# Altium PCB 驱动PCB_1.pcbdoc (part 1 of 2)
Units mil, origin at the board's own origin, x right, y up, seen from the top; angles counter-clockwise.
Board outline 1900 x 3705 mil, 2 copper layers (Top Layer, Bottom Layer); 43 components, 46 nets, 190 pads, 128 vias.
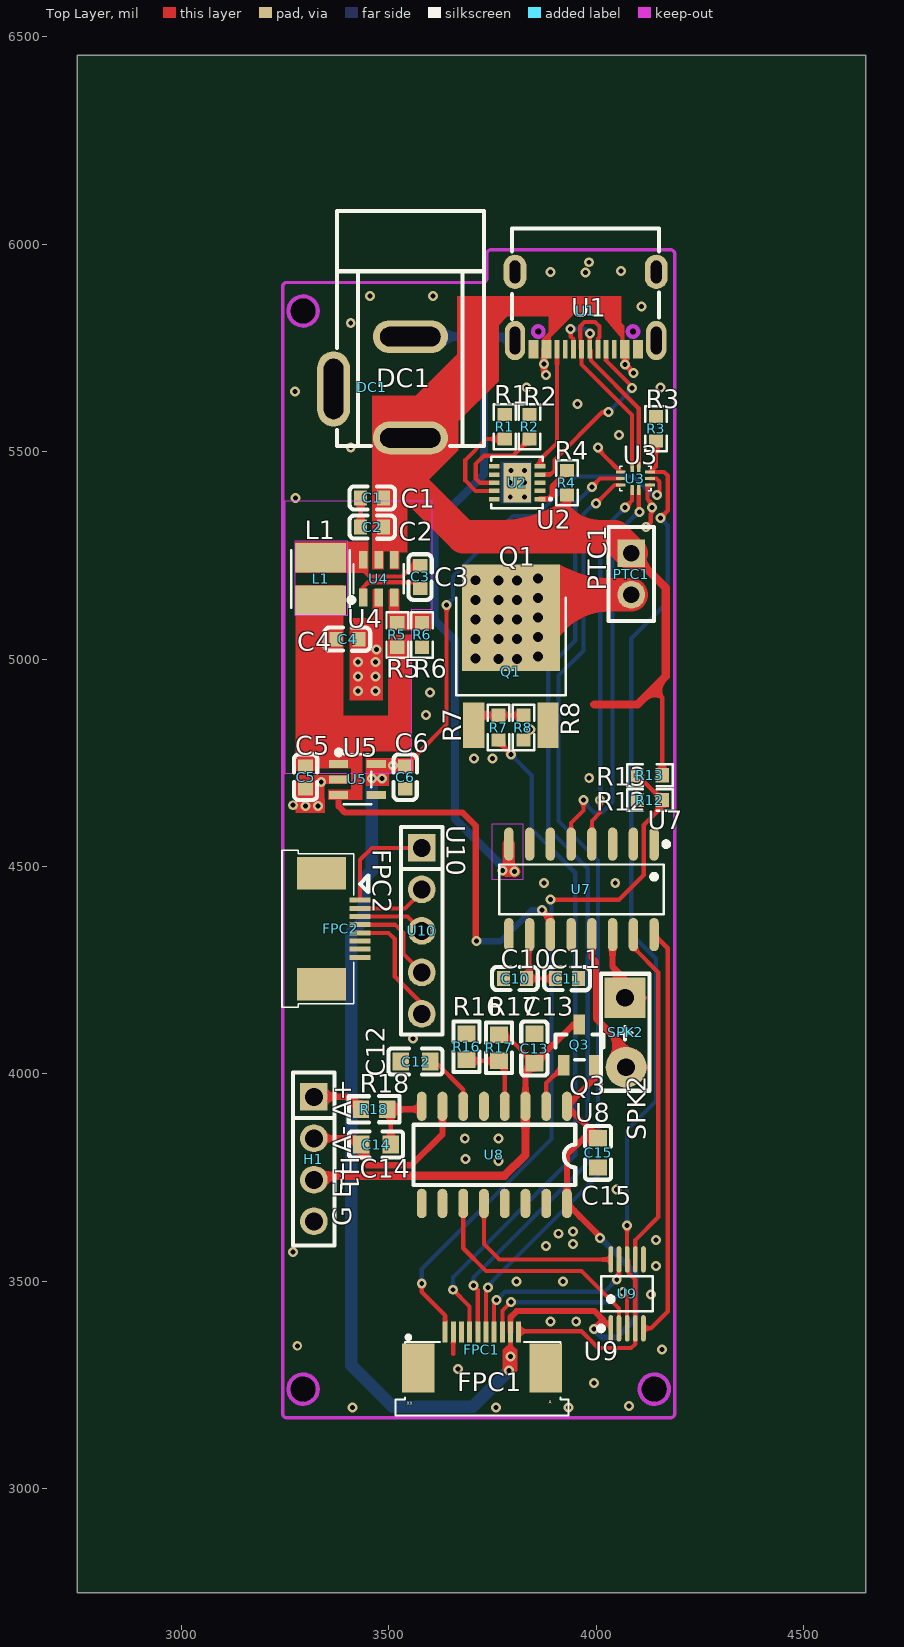
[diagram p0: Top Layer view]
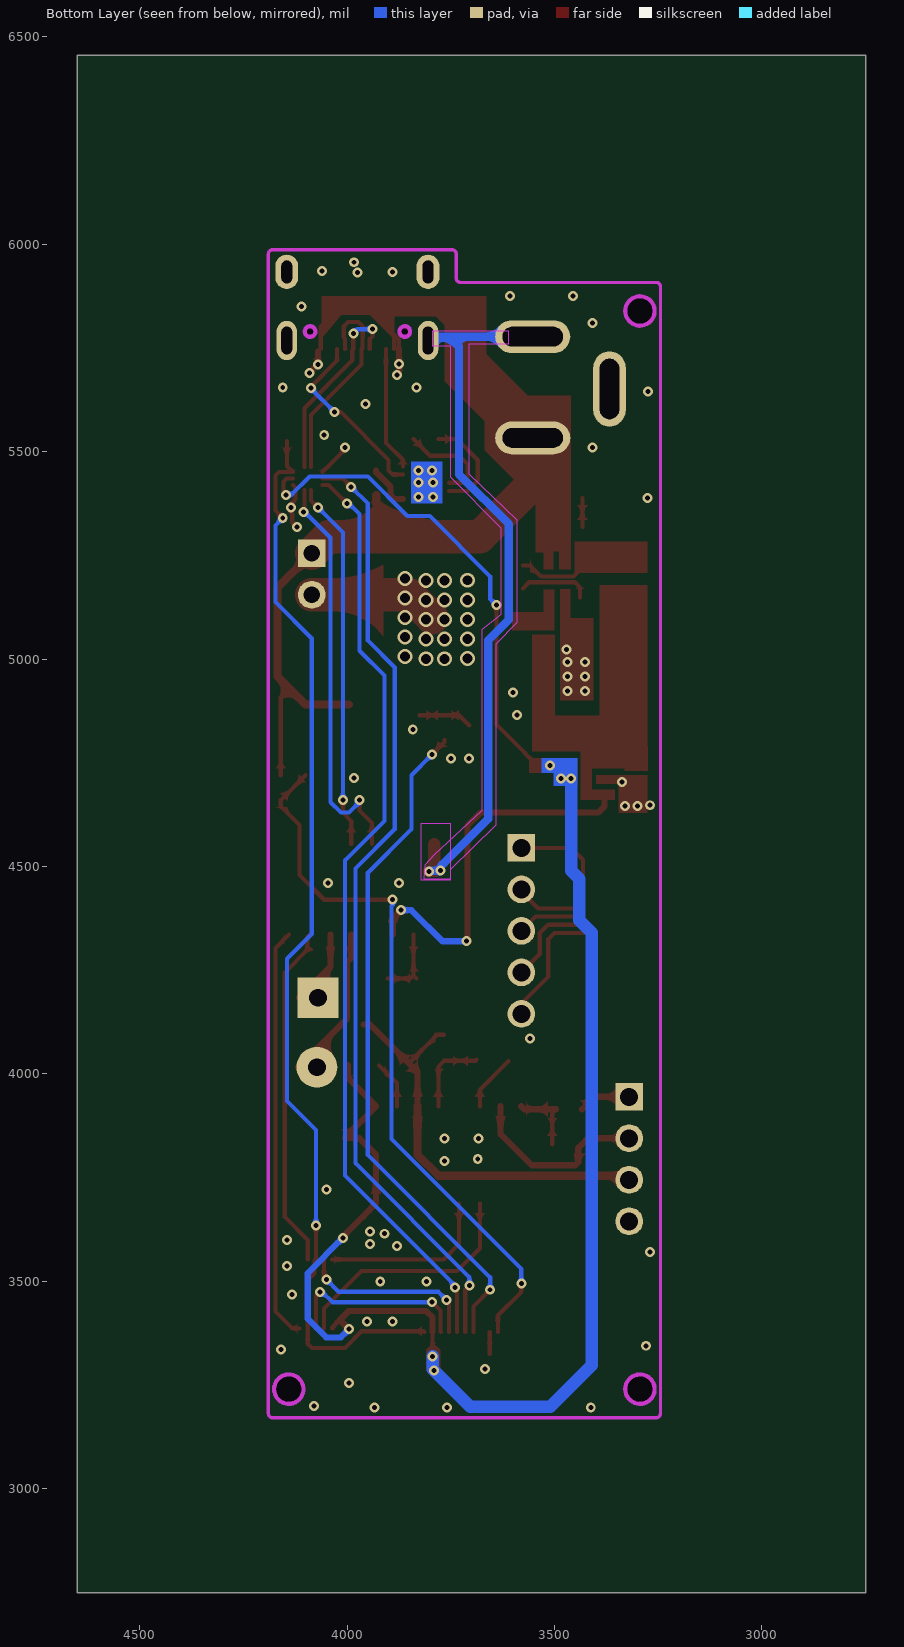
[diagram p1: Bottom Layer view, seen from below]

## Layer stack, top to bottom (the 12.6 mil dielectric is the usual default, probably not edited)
Top Layer: signal copper (thickness not stored)
Dielectric: dielectric 12.6, FR-4, Dk 4.8
Bottom Layer: signal copper (thickness not stored)

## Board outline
4650,2750 2750,2750 2750,6455 4650,6455
cut-out: 3329.43,5838.89 ccw(c3294,5838.67) 3258.57,5838.89 ccw(c3294,5839.11)
cut-out: 3329.43,3240.47 ccw(c3294,3240.25) 3258.57,3240.47 ccw(c3294,3240.69)
cut-out: 4175.89,3240.47 ccw(c4140.45,3240.47) 4105.02,3240.47 ccw(c4140.45,3240.47)

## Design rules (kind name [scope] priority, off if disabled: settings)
BoardOutlineClearance copperThickness1oz [All] p0: genericclearance=10 ignorepadtopadclearanceinfootprint=FALSE except(0: Arc-SplitContinuation Track-SplitContinuation SMDPad-SplitContinuation THPad-SplitContinuation Via-SplitContinuation Fill-SplitContinuation Poly-SplitContinuation Region-SplitContinuation Text-SplitContinuation; 6: Track-CutoutEdge SMDPad-CutoutEdge THPad-CutoutEdge Via-CutoutEdge Region-CutoutEdge; 11.8: Track-OutlineEdge SMDPad-OutlineEdge THPad-OutlineEdge Via-OutlineEdge Fill-OutlineEdge Region-OutlineEdge Poly-OutlineEdge Text-OutlineEdge Fill-CutoutEdge)
BoardOutlineClearance copperThickness2oz [All] p0: genericclearance=10 ignorepadtopadclearanceinfootprint=FALSE except(0: Arc-SplitContinuation Track-SplitContinuation SMDPad-SplitContinuation THPad-SplitContinuation Via-SplitContinuation Fill-SplitContinuation Poly-SplitContinuation Region-SplitContinuation Text-SplitContinuation; 6: Track-CutoutEdge SMDPad-CutoutEdge THPad-CutoutEdge Via-CutoutEdge Region-CutoutEdge; 11.8: Track-OutlineEdge SMDPad-OutlineEdge THPad-OutlineEdge Via-OutlineEdge Fill-OutlineEdge Region-OutlineEdge Poly-OutlineEdge Text-OutlineEdge Fill-CutoutEdge)
Clearance copperThickness1oz [(InNet('GND') OR InNet('3V3') OR InNet('ADC_VIN') OR InNet('$2N1457') OR InNet('$2N1458') OR InNet('VIN') OR InNet('5V') OR InNet('$2N1719') OR InNet('$2N3514') OR InNet('$2N3517') OR InNet('A-') OR InNet('ESP_TX') OR InNet('ESP_RX') OR InNet('DN1') OR InNet('DP1') OR InNet('A+') OR InNet('E+') OR InNet('$2N173') OR InNet('$2N169') OR InNet('$2N860') OR InNet('$2N846') OR InNet('$2N1461') OR InNet('$2N861') OR InNet('DAC') OR InNet('$2N3512') OR InNet('SPK2') OR InNet('SPK1') OR InNet('SCK') OR InNet('DOUT') OR InNet('CC1') OR InNet('DN') OR InNet('DP') OR InNet('CC2') OR InNet('USBDM') OR InNet('USBDP') OR InNet('CH7800_RX') OR InNet('CH7800_TX') OR InNet('SW') OR InNet('PTC') OR InNet('$2N3503') OR InNet('$2N3080') OR InNet('GPIO17') OR InNet('GPIO16') OR InNet('GPIO15') OR InNet('GPIO14') OR InNet('GPIO8'))] p1: gap=7 ignorepadtopadclearanceinfootprint=FALSE except(4: Track-Track; 6: Track-SMDPad SMDPad-SMDPad Track-THPad SMDPad-THPad THPad-THPad Track-Via SMDPad-Via THPad-Via Via-Via SMDPad-Fill THPad-Fill Via-Fill Fill-Fill Track-Region SMDPad-Region THPad-Region Via-Region Region-Region Track-Poly SMDPad-Poly THPad-Poly Via-Poly Fill-Poly Region-Poly Poly-Poly Track-Text SMDPad-Text THPad-Text Via-Text Fill-Text Region-Text Poly-Text Text-Text; 6.9: Track-Hole SMDPad-Hole THPad-Hole Via-Hole Fill-Hole Region-Hole Poly-Hole Text-Hole Sheet-Hole; 11.8: Track-Fill Fill-Region Track-Sheet SMDPad-Sheet THPad-Sheet Via-Sheet Fill-Sheet Region-Sheet Poly-Sheet Text-Sheet)
Clearance copperThickness2oz [All] p1: gap=7 ignorepadtopadclearanceinfootprint=FALSE except(6: Track-SMDPad SMDPad-SMDPad Track-THPad SMDPad-THPad THPad-THPad Track-Via SMDPad-Via THPad-Via Via-Via SMDPad-Fill THPad-Fill Via-Fill Fill-Fill Track-Region SMDPad-Region THPad-Region Via-Region Region-Region Track-Poly SMDPad-Poly THPad-Poly Via-Poly Fill-Poly Region-Poly Poly-Poly Track-Text SMDPad-Text THPad-Text Via-Text Fill-Text Region-Text Poly-Text Text-Text; 6.9: Track-Hole SMDPad-Hole THPad-Hole Via-Hole Fill-Hole Region-Hole Poly-Hole Text-Hole Sheet-Hole; 8: Track-Track; 11.8: Track-Fill Fill-Region Track-Sheet SMDPad-Sheet THPad-Sheet Via-Sheet Fill-Sheet Region-Sheet Poly-Sheet Text-Sheet)
DiffPairsRouting differentialPair [All] p1: maxuncoupledlength=10 minlimit=6 maxlimit=6 mostfreqgap=6 toplayer_minwidth=5 toplayer_prefwidth=10 toplayer_maxwidth=100 bottomlayer_minwidth=5 bottomlayer_prefwidth=10 bottomlayer_maxwidth=100
PasteMaskExpansion pasteMaskExpansion [All] p1: expansion=0
PlaneConnect innerPlane [All] p1: planeconnectstyle=Relief reliefexpansion=20 reliefentries=4 reliefconductorwidth=10 reliefairgap=10
PolygonConnect copperRegion [All] p1: connectstyle=Relief reliefentries=4 reliefconductorwidth=10 polygonreliefangle="90 Angle" airgapwidth=10
RoutingVias viaSize [All] p1: viastyle="Through Hole" holewidth=12.0078 minholewidth=11.811 maxholewidth=248.0314 width=24.0158 minwidth=19.685 maxwidth=393.7008
SolderMaskExpansion solderMaskExpansion [All] p1: useseparateexpansions=TRUE expansion=2 expansionbottom=2
Width copperThickness1oz [All] p1: maxlimit=100 minlimit=5 preferedwidth=10
Width copperThickness2oz [All] p1: maxlimit=100 minlimit=8 preferedwidth=10

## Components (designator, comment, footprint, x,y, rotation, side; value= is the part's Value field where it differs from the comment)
C1 "CC0603KRX7R9BB104" C0603#1 3460.47,5388.23 r180 top
C2 "CL10A106MA8NRNC" C0603#1 3460.47,5318.23 r180 top
C3 "CC0603KRX7R9BB104" C0603#1 3576.08,5198.01 r90 top
C4 "CC0603KRX7R9BB104" C0603#1 3401.08,5048.01 r0 top
C5 "CL10A106MA8NRNC" C0603#1 3300,4715 r270 top
C6 "CL10A106MA8NRNC" C0603#1 3540,4715 r270 top
C10 "CAP_0603" C0603#1 3805,4230 r0 top
C11 "CAP_0603" C0603#1 3930,4230 r180 top
C12 "100nF" C0603#2 3565,4030 r180 top
C13 "10uF" C0603#2 3851.24,4061.24 r90 top
C14 "100nF" C0603#2 3470,3830 r180 top
C15 "10uF" C0603#2 4005,3810 r270 top
DC1 "DC005" DC-IN-TH_DC005 3460,5655 r270 top locked
FPC1 "F0501-T-10-20T-R" FPC-SMD_F0501-T-10-20T-R 3725,3335 r0 top
FPC2 "F0501-T-08-20T-R" FPC-SMD_8P-P0.50_L4.4-W9.6 3385,4350 r270 top
H1 "HDR-F_2.54_1x4P" hdr-th_4p-p2.54-v-f 3320,3795 r270 top
L1 "CD32-4R7M 4.7UH" IND-SMD_L3.5-W3.0 3336.08,5193.01 r90 top
PTC1 "HDR-F_2.54_1x2P" HDR-TH_2P-P2.54-V-F 4085,5205 r270 top
Q1 "AOD4184L" TO-252-2_L6.6-W6.1-P4.57-LS9.9-TL-CW 3795,4970 r90 top
Q3 "S8550" SOT-23-3_L2.9-W1.6-P1.90-LS2.8-BR 3960,4070 r270 top
R1 "Res_0603" R0603#1 3780,5560 r90 top
R2 "Res_0603" R0603#1 3840,5560 r90 top
R3 "Res_0603" R0603#1 4145,5555 r270 top
R4 "Res_0603" R0603#1 3930,5425 r270 top
R5 "Res_0603" R0603#1 3521.08,5058.01 r270 top
R6 "Res_0603" R0603#1 3581.08,5058.01 r90 top
R7 "Res_0603" R0603#1 3765,4835 r90 top
R8 "Res_0603" R0603#1 3825,4835 r270 top
R12 "Res_0603" R0603#1 4130,4660 r180 top
R13 "Res_0603" R0603#1 4130,4720 r180 top
R16 "8.2K" R0603#2 3687.88,4065.74 r270 top
R17 "20K" R0603#2 3766.24,4063.24 r90 top
R18 "1K" R0603#2 3465,3915 r0 top
SPK2 "GSPK3013P-8R0.15W" SPK-TH_BD30.0-P15.00-D0.8-L-RD 4070,4100 r270 top
U1 "TYPE-C16PIN母座 板上四脚三次molding" USB-SMD_TYPE-C16PIN 3975,5840 r180 top locked
U2 "HUSB238-002D" TDFN-10_L3.0-W3.0-P0.50-BL-EP 3810,5425 r90 top
U3 "BL1532TQFN" qfn_10 4095,5435 r180 top
U4 "RY8411_C2935411" SOT-23-6_L2.9-W1.6-P0.95-LS2.8-TL 3476.14,5193.63 r90 top
U5 "ME6212C33M5G" SOT-23-5_L3.0-W1.7-P0.95-LS2.8-BL 3425,4710 r270 top
U7 "CH7800" SOP-16_L9.9-W3.9-P1.27-LS6.0-BL 3965,4445 r180 top
U8 "HX711" SOP-16_L10.0-W3.9-P1.27-LS6.0-BL 3755,3805 r180 top
U9 "BL1555MM" MSOP-10_L3.0-W3.0-P0.50-LS5.0-BL 4075,3470 r0 top
U10 "HB-PH3-25415PB2GOP" HDR-TH_5P-P2.54-V-M 3580,4345 r270 top

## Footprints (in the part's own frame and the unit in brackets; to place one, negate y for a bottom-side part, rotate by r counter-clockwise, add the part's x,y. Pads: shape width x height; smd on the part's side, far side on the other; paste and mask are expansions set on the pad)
C0603#1 [mm]
  rect 0.8x0.9 smd: 1(-0.7,0) 2(0.7,0)
  silkscreen extent -1.41,-0.71 1.39,0.72
C0603#2 [mm]
  rect 1x1.1 smd: 1(-0.9,0) 2(0.9,0)
  silkscreen extent -1.65,-0.8 1.65,0.8
DC-IN-TH_DC005 [mm]
  oval 2x4.6 hole 1.2 slot 3.7 at 90 deg: 1(3.1,2.35) 2(-3.1,2.35)
  oval 4.6x2 hole 1.2 slot 3.7 at 0 deg: 3(0.1,-2.35)
  silkscreen extent -10.8,-2.15 3.6,6.85
FPC-SMD_8P-P0.50_L4.4-W9.6 [mm]
  rect 2x3 smd: 0(-3.4,-1.175) 0(3.4,-1.175)
  rect 0.3x1.3 smd: 1(-1.75,1.175) 2(-1.25,1.175) 3(-0.75,1.175) 4(-0.25,1.175) 5(0.25,1.175) 6(0.75,1.175) 7(1.25,1.175) 8(1.75,1.175)
  silkscreen extent -4.8,-3.6 4.8,1.68
FPC-SMD_F0501-T-10-20T-R [mm]
  rect 0.3x1.3 smd: 1(-2.25,1.097) 2(-1.75,1.097) 3(-1.25,1.097) 4(-0.75,1.097) 5(-0.25,1.097) 6(0.25,1.097) 7(0.75,1.097) 8(1.25,1.097) 9(1.75,1.097) 10(2.25,1.097)
  rect 2x3 smd: 11(3.9,-1.097) 12(-3.9,-1.097)
  silkscreen extent -5.3,-4.03 5.3,0.87
HDR-TH_2P-P2.54-V-F [mm]
  rect 1.7x1.7 hole 1: 1(-1.27,0)
  round 1.7 hole 1: 2(1.27,0)
  silkscreen extent -2.88,-1.39 2.88,1.4
hdr-th_4p-p2.54-v-f [mm]
  rect 1.7x1.7 hole 1.1: 1(-3.81,0)
  round 1.7 hole 1.1: 2(-1.27,0) 3(1.27,0) 4(3.81,0)
  silkscreen extent -5.29,-1.27 5.29,1.27
HDR-TH_5P-P2.54-V-M [mm]
  rect 1.7x1.7 hole 1.1: 1(-5.08,0)
  round 1.7 hole 1.1: 2(-2.54,0) 3(0,0) 4(2.54,0) 5(5.08,0)
  silkscreen extent -6.35,-1.27 6.35,1.27
IND-SMD_L3.5-W3.0 [mm]
  rect 1.8x3.12 smd: 1(1.303,0) 2(-1.303,0)
  silkscreen extent -1.75,-1.8 1.75,1.8
MSOP-10_L3.0-W3.0-P0.50-LS5.0-BL [mm]
  oval 0.28x1.62 smd: 1(-1,-2.11) 2(-0.5,-2.11) 3(0,-2.11) 4(0.5,-2.11) 5(1,-2.11) 6(1,2.11) 7(0.5,2.11) 8(0,2.11) 9(-0.5,2.11) 10(-1,2.11)
  silkscreen extent -1.74,-2.26 1.58,1.07
qfn_10 [mm]
  rrect20% 0.2x0.6 smd: 1(-0.2,-0.7) 2(0.2,-0.7) 6(0.2,0.7) 7(-0.2,0.7)
  rrect20% 0.6x0.2 smd: 3(0.9,-0.4) 4(0.9,0) 5(0.9,0.4) 8(-0.9,0.4) 9(-0.9,0) 10(-0.9,-0.4)
  silkscreen extent -0.95,-0.89 0.95,0.75
R0603#1 [mil]
  rect 31.75x34.02 smd: 1(-29.66,0) 2(29.66,0)
  silkscreen extent -55,-26 55,26
R0603#2 [mil]
  rect 39.37x43.31 smd: 1(-31.49,0) 2(31.5,0)
  silkscreen extent -61,-31 61,32
SOP-16_L9.9-W3.9-P1.27-LS6.0-BL [mil]
  oval 22.6x80.24 smd: 1(-175,-109.02) 2(-125,-109.02) 3(-75,-109.02) 4(-25,-109.02) 5(25,-109.02) 6(75,-109.02) 7(125,-109.02) 8(175,-109.02) 9(175,109.02) 10(125,109.02) 11(75,109.02) 12(25,109.02) 13(-25,109.02) 14(-75,109.02) 15(-125,109.02) 16(-175,109.02)
  silkscreen extent -210,-115 198,60
SOP-16_L10.0-W3.9-P1.27-LS6.0-BL [mm]
  oval 0.6x1.8 smd: 1(-4.445,-2.972) 2(-3.175,-2.972) 3(-1.905,-2.972) 4(-0.635,-2.972) 5(0.635,-2.972) 6(1.905,-2.972) 7(3.175,-2.972) 8(4.445,-2.972) 9(4.445,2.972) 10(3.175,2.972) 11(1.905,2.972) 12(0.635,2.972) 13(-0.635,2.972) 14(-1.905,2.972) 15(-3.175,2.972) 16(-4.445,2.972)
  silkscreen extent -4.95,-1.85 4.95,1.85
SOT-23-3_L2.9-W1.6-P1.90-LS2.8-BR [mm]
  rect 1.25x0.7 smd: 1(1.25,-0.95) 2(1.25,0.95) 3(-1.25,0)
  silkscreen extent -0.65,-1.46 0.9,1.46
SOT-23-5_L3.0-W1.7-P0.95-LS2.8-BL [mm]
  rect 0.49x1.157 smd: 1(-0.95,-1.154) 2(0,-1.154) 3(0.95,-1.154)
  rect 0.49x1.175 smd: 4(0.95,1.154) 5(-0.95,1.154)
  silkscreen extent -1.8,-1.29 1.53,0.85
SOT-23-6_L2.9-W1.6-P0.95-LS2.8-TL [mil]
  rect 42.2x20.95 smd: 1(-45.24,37.4) 2(-45.24,0) 3(-45.24,-37.4) 4(45.24,-37.4) 5(45.24,0) 6(45.24,37.4)
  silkscreen extent -57,-61 35,72
SPK-TH_BD30.0-P15.00-D0.8-L-RD [mm]
  rect 2.5x2.5 hole 1.1: 1(-2.128,0)
  round 2.5 hole 1.1: 2(2.128,0.064)
  silkscreen extent -3.59,-1.47 3.57,1.5
TDFN-10_L3.0-W3.0-P0.50-BL-EP [mm]
  rect 0.28x0.665 smd: 1(-1,-1.407) 2(-0.5,-1.407) 3(0,-1.407) 4(0.5,-1.407) 5(1,-1.407) 6(1,1.407) 7(0.5,1.407) 8(0,1.407) 9(-0.5,1.407) 10(-1,1.407)
  rect 2.4x1.7 smd: 11(0,0)
  silkscreen extent -1.58,-2.12 1.58,1.58
TO-252-2_L6.6-W6.1-P4.57-LS9.9-TL-CW [mm]
  rect 2.8x1.3 smd: 1(-3.292,2.273) 3(-3.292,-2.273)
  rect 6.5x6 smd: 2(3.292,0)
  silkscreen extent -1.46,-3.35 4.51,3.34
USB-SMD_TYPE-C16PIN [mm]
  oval 1.25x2.4 hole 0.65 slot 1.7 at 90 deg: 17(-4.325,1.835) 18(4.325,1.835)
  oval 1.4x2.1 hole 0.65 slot 1.4 at 90 deg: 19(-4.325,-2.365) 20(4.325,-2.365)
  rect 0.3x1.15 smd: A1(-3.35,2.365) A4(-2.55,2.365) A5(-1.25,2.365) A6(-0.25,2.365) A7(0.25,2.365) A8(1.25,2.365) A9(2.55,2.365) A12(3.35,2.365) B1(3.05,2.365) B4(2.25,2.365) B5(1.75,2.365) B6(0.75,2.365) B7(-0.75,2.365) B8(-1.75,2.365) B9(-2.25,2.365) B12(-3.05,2.365)
  Board Outline Layer circle w0.005: c-2.9,1.285 r0.325
  Board Outline Layer circle w0.005: c2.9,1.285 r0.325
  Board Outline Layer circle w0.254: c-2.9,1.285 r0.325
  Board Outline Layer circle w0.254: c2.9,1.285 r0.325
  Multi-Layer board cut-out: -3.225,1.285 -3.179,1.125 -3.061,1.009 -2.9,0.967 -2.739,1.009 -2.621,1.125 -2.575,1.285 -2.575,1.285 -2.621,1.445 -2.739,1.561 -2.9,1.604 -3.061,1.561 -3.179,1.445 -3.225,1.285
  Multi-Layer board cut-out: 2.575,1.285 2.621,1.125 2.739,1.009 2.9,0.967 3.06,1.009 3.179,1.125 3.225,1.285 3.225,1.285 3.179,1.445 3.06,1.561 2.9,1.604 2.739,1.561 2.621,1.445 2.575,1.285
  silkscreen extent -4.5,-5.01 4.5,0.52

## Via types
v1: diameter 24.02, hole 12.01, Top Layer to Bottom Layer, 108 vias
v2: diameter 36, hole 24, Top Layer to Bottom Layer, 20 vias

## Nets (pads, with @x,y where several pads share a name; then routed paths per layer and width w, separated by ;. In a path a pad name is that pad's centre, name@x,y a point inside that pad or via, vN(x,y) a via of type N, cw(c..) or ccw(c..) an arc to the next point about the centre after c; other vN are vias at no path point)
3V3: C6.1 C15.1 FPC1.9 Q3.2 U3.9 U5.5 U8.1 U8.16 U9.1 | length 4414
  Top Layer w10: C6.1@3540,4742.56 3558.64,4761.2 3560.45,4761.2 3570.3,4771.05 3570.3,4772.86 3640,4842.56 v1(3640,5130) ; v1(3793.89,3319.35) FPC1.9@3793.89,3378.18 ; 4017.91,3407.09 4035.63,3389.37 U9.1@4035.63,3386.93 ; U3.9@4130.43,5435 4145.49,5435 4153.22,5427.27 4153.22,5401.21 v1(4147.01,5395)
  Top Layer w15: FPC1.9@3793.89,3378.18 3793.89,3413.48 3808.89,3428.48 3996.52,3428.48 4017.91,3407.09 4017.09,3407.09 v1(3995,3385) ; Q3.2@3997.4,4020.8 3997.4,3989.4 U8.1@3930,3922 4005,3847 C15.1@4005,3845.43 3970.43,3845.43 3930,3805 U8.16@3930,3688 4010,3608 v1(4010,3605)
  Bottom Layer w10: v1(3640,5130) 3655,5145 3655,5199.4 3800.6,5345 3855,5345 3950,5440 4090,5440 4135,5395 v1(4147.01,5395)
  Bottom Layer w15: v1(3995,3385) 4015,3365 4050,3365 4095,3410 4095,3520 v1(4010,3605)
  Bottom Layer w30: v1(3460,4712.56) 3460,4490 3440,4470 3440,4370 3410,4340 3410,3298.39 3510,3198.39 3703.39,3198.39 v1(3790,3285) 3793.89,3288.89 v1(3793.89,3319.35)
  other v1: 3484.55,4711.86 3510.37,4743.32
5V: C4.1 C5.1 L1.2 R5.2 U5.1 U5.3 U7.11 | length 911.7
  Top Layer w15: U5.3@3379.58,4672.6 3379.58,4645.42 3395,4630 3678.34,4630 3710,4598.34 v1@3710,4320 ; v1(3870,4395) 3890,4375 U7.11@3890,4335.98
  Bottom Layer w15: v1(3712.14,4320) 3770,4320 3845,4395 v1(3870,4395)
$2N169: Q1.1 R7.2 R8.1 | length 129.5
  Top Layer w10: Q1.1@3705.52,4840.4 3729.78,4864.66 R7.2@3765,4864.66 R8.1@3825,4864.66
$2N173: PTC1.2 Q1.2 | length 312.9
  Top Layer w80: Q1.2@3795,5099.6 3850.39,5155 PTC1.2@4085,5155
  other v2: 3710,5001.42 3765,5000.71 3810,5000.71 3860,5005.71 3765,5047.85 3810,5047.85 3710,5048.56 3860,5052.85 3765,5095 3810,5095 3710,5095.71 3860,5100 3765,5142.15 3810,5142.15 3710,5142.85 3860,5147.15 3765,5189.29 3810,5189.29 3710,5190 3860,5194.29
$2N846: R4.1 U2.1 | length 107.6
  Top Layer w15: U2.1@3865.41,5385.63 3885.63,5385.63 3895,5395 3895,5415.22 3930,5450.22 R4.1@3930,5454.66
$2N860: R1.1 U2.9 | length 245.7
  Top Layer w10: U2.9@3754.59,5405.32 3709.68,5405.32 3685,5430 3685,5480 3735.34,5530.34 R1.1@3780,5530.34
$2N861: R2.1 U2.8 | length 238.7
  Top Layer w10: U2.8@3754.59,5425 3720,5425 3710,5435 3710,5470 3730,5490 3799.66,5490 R2.1@3840,5530.34
$2N1457: C3.2 L1.1 U4.6 | length 178.9
  Top Layer w10: U4.6@3438.74,5238.87 3444.36,5233.26 3444.36,5209.02 3454.2,5199.17 3532.39,5199.17 3558.79,5225.57 C3.2@3576.08,5225.57
$2N1458: C3.1 U4.1 | length 173
  Top Layer w10: U4.1@3438.74,5148.39 3438.74,5172.82 3451.08,5185.15 3561.38,5185.15 C3.1@3576.08,5170.45
$2N1461: R5.1 R6.2 U4.3
$2N1719: C10.2 C11.2 U7.10 | length 174.6
  Top Layer w10: C10.2@3832.56,4230 C10.2@3840,4237.44 ; U7.10@3840,4335.98 C10.2@3840,4237.44 ; C11.2@3902.44,4230 3847.44,4230 C10.2@3840,4237.44
$2N3080: FPC1.3
$2N3503: Q3.1 U8.2 | length 116.4
  Top Layer w10: U8.2@3880,3922 3880,3978.2 Q3.1@3922.6,4020.8
$2N3512: R16.2 R17.1 U8.4 | length 194.8
  Top Layer w10: R16.2@3687.88,4034.24 3690.38,4031.75 R17.1@3766.24,4031.75 3780,4017.98 U8.4@3780,3922
$2N3514: C12.1 U8.6 | length 137.3
  Top Layer w10: C12.1@3611.24,4030.81 3680,3962.04 U8.6@3680,3922
$2N3517: C14.1 R18.2 U8.8 | length 175.1
  Top Layer w10: R18.2@3496.5,3915 3505.43,3906.07 C14.1@3505.43,3830
  Top Layer w15: R18.2@3496.5,3915 3573,3915 U8.8@3580,3922
A+: H1.1 R18.1 | length 125.9
  Top Layer w15: H1.1@3320,3945 3403.51,3945 R18.1@3433.51,3915
A-: C14.2 H1.2 U8.7 | length 455.2
  Top Layer w15: H1.2@3320,3845 3419.56,3845 C14.2@3434.56,3830 3442.93,3821.63 3442.93,3787.07 3450,3780 3555,3780 3630,3855 U8.7@3630,3922
ADC_VIN: FPC1.1 R12.1 R13.2 | length 1729
  Top Layer w10: v1(3580,3495) 3580,3475 3636.41,3418.59 FPC1.1@3636.41,3378.18 ; v1(3890,4420) 4055,4420 4115,4480 4115,4600 4159.66,4644.66 R12.1@4159.66,4660 4159.66,4660.68 R13.2@4100.34,4720
  Bottom Layer w10: v1(3580,3495) 3580,3530 3892.99,3842.99 3892.99,4404.52 3890,4407.52 v1(3890,4420)
CC1: U1.A5 U2.4 | length 442.7
  Top Layer w10: U2.4@3865.41,5444.69 3890,5444.69 3900,5454.69 3900,5480 4015,5595 v1(4030,5595) ; U1.A5@4024.21,5746.88 4024.21,5719.56 4086.38,5657.39 v1(4086.38,5653.47)
  Bottom Layer w10: v1(4030,5595) 4086.38,5651.38 v1(4086.38,5653.47)
CC2: U1.B5 U2.5 | length 299.4
  Top Layer w10: U2.5@3865.41,5464.37 3865.41,5480.41 3906.1,5521.1 U1.B5@3906.1,5746.88
CH7800_RX: U7.16 U9.5 | length 997.2
  Top Layer w10: U9.5@4114.37,3386.93 4131.93,3386.93 4172.86,3427.86 4172.86,4303.12 U7.16@4140,4335.98
CH7800_TX: U7.15 U9.7 | length 830.7
  Top Layer w10: U7.15@4090,4335.98 4095,4330.98 4095,4300 4150,4245 4150,3655 4094.69,3599.69 U9.7@4094.69,3553.07
DAC: U7.9
DN: U1.A7 U1.B7 U3.2 | length 502.2
  Top Layer w10: U1.B7@4004.53,5746.88 4005,5747.35 4005,5772.48 4007.99,5775.48 4007.99,5802.01 3997.93,5812.07 3972.07,5812.07 3962.01,5802.01 3962.01,5775.48 3962.93,5774.56 3962.93,5749.11 U1.A7@3965.16,5746.88 3965.16,5709.84 4087.13,5587.87 U3.2@4087.13,5462.56
DN1: FPC1.5 U3.4 | length 2315.6
  Top Layer w10: v1(3705,3490) 3715.16,3479.84 FPC1.5@3715.16,3378.18 ; v1(3990,5415) 4010,5435 U3.4@4059.57,5435
  Bottom Layer w10: v1(3705,3490) 3705,3510 3980,3785 3980,4495 3885,4590 3885,4980 3950,5045 3950,5375 v1(3990,5415)
DOUT: U8.12 U9.10 | length 418.9
  Top Layer w10: U8.12@3730,3688 3730,3590 3766.93,3553.07 U9.10@4035.63,3553.07
DP: U1.A6 U1.B6 U3.1 | length 472.3
  Top Layer w10: v1(3939.02,5795) 3939.02,5777.73 3945.47,5771.28 U1.B6@3945.47,5746.88 ; v1(3985,5785) 3985,5747.04 U1.A6@3984.84,5746.88 3987.64,5744.08 3987.64,5719.69 4102.87,5604.46 U3.1@4102.87,5462.56
  Bottom Layer w10: v1(3939.02,5795) 3975,5795 v1(3985,5785)
DP1: FPC1.6 U3.5 | length 2266.2
  Top Layer w10: FPC1.6@3734.84,3378.18 3734.84,3479.84 v1(3740,3485) ; v1(4000,5375) 4044.25,5419.25 U3.5@4059.57,5419.25
  Bottom Layer w10: v1(3740,3485) 3740,3490 4005,3755 4005,4515 3910,4610 3910,4960 3970,5020 3970,5350 3995,5375 v1(4000,5375)
E+: C13.1 H1.3 Q3.3 R17.2 U8.3 | length 1025.5
  Top Layer w10: R17.2@3766.24,4094.74 3782.31,4094.74 C13.1@3851.24,4025.81
  Top Layer w15: U8.3@3830,3922 3830,4004.57 C13.1@3851.24,4025.81 3944.63,4119.2 Q3.3@3960,4119.2
  Top Layer w20: H1.3@3320,3745 3330,3755 3780,3755 3830,3805 U8.3@3830,3922
ESP_RX: FPC1.7 U9.9 | length 440.1
  Top Layer w10: FPC1.7@3754.53,3378.18 3754.53,3449.53 v1(3760,3455) ; v1(4050,3505) 4055.32,3510.32 U9.9@4055.32,3553.07
  Bottom Layer w10: v1(3760,3455) 3780,3475 4020,3475 v1(4050,3505)
ESP_TX: FPC1.8 U9.3 | length 453
  Top Layer w10: FPC1.8@3774.22,3378.18 3775,3378.96 3775,3430 v1(3795,3450) ; v1(4065,3475) 4075,3465 U9.3@4075,3386.93
  Bottom Layer w10: v1(3795,3450) 4035,3450 4060,3475 v1(4065,3475)
GND: C1.2 C2.2 C4.2 C5.2 C6.2 C10.1 C11.1 C12.2 C13.2 C15.2 DC1.2 DC1.3 FPC1.2 FPC1.11 FPC1.12 FPC2.0 H1.4 Q1.3 R1.2 R2.2 R3.1 R6.1 R8.2 R12.2 R16.1 U1.17 U1.18 U1.19 U1.20 U1.A1 U1.A12 U1.B1 U1.B12 U2.11 U3.3 U3.8 U4.2 U5.2 U7.8 U7.12 U8.5 U8.14 U8.15 U9.6 | length 2104.5
  Top Layer w10: C2.2@3432.91,5318.23 C1.2@3432.91,5388.23 ; 3656.11,3325 FPC1.2@3656.11,3378.18 ; v1(4005,5510) 4005,5505.32 U3.3@4059.57,5450.75 ; v1(4120.18,5317.75) 4132.01,5329.58 4132.01,5349.52 4135,5352.52 v1(4135,5365) 4135,5374.49 4124.02,5385.48 4124.02,5412.84 U3.8@4130.43,5419.25
  Top Layer w30: U7.8@3790,4554.02 3790,4495 3785,4490 3800.97,4490 v1(3802.99,4487.98)
  Bottom Layer w20: DC1.2@3552.53,5777.04 3753.47,5777.04 ; v1(3802.99,4487.98) 3800.97,4490 v1(3775,4490) 3775,4500 3660,4615 3660,5045 3610,5095 3610,5325 3730,5445 3730,5753.57 3753.47,5777.04 ; U1.18@3804.72,5767.75 3795.43,5777.04 3753.47,5777.04
  other v1: 3412.64,3196.09 3758.66,3196.09 3933.66,3196.09 4080,3200 3995,3255 3667.76,3288.86 4158.89,3335.68 3280,3345 3890,3402.99 3952.34,3402.99 4132.67,3468.54 3808.8,3500 3920,3500 4145,3537 3270,3571.12 3880,3585 3945,3590 4145,3600 3910,3615 3945,3620 4049.1,3722.17 3765,3790 3685,3795 3683.69,3845 3765,3845 3558.89,4085.68 3875,4460 4046.38,4460 3299.99,4645.61 3329.71,4645.61 3270,4647.71 3337.81,4703.97 3983.68,4713.29 3706.46,4760 3750,4760 3841.65,4830.79 3590,4865 3599.79,4919.75 3426.08,4923.01 3468.75,4923.01 3426.08,4958.01 3468.4,4958.01 3426.15,4992.65 3468.4,4992.65 3471.08,5023.01 3275.62,5388.64 3793.33,5391.01 3827.51,5391.01 3793.33,5425 3827.51,5425 3795,5455 3827.51,5455 3408.89,5509.44 4055,5540 3955,5615 3275,5645 3832.08,5654.09 4155,5655 3408.89,5809.44 4110,5850 3455,5875 3607.59,5875 3975,5932.11 3890.29,5933.12 4060,5935 3983.37,5956.38
GPIO8: FPC2.1 U10.1 | length 258
  Top Layer w10: FPC2.1@3431.26,4418.9 3431.26,4516.26 3460,4545 U10.1@3580,4545
GPIO14: FPC2.2 U10.2 | length 170.6
  Top Layer w10: FPC2.2@3431.26,4399.22 3539.22,4399.22 3580,4440 U10.2@3580,4445
GPIO15: FPC2.3 U10.3 | length 163
  Top Layer w10: FPC2.3@3431.26,4379.52 3545.47,4379.52 U10.3@3580,4345
GPIO16: FPC2.4 U10.4 | length 225.6
  Top Layer w10: FPC2.4@3431.26,4359.85 3515.16,4359.85 3535.55,4339.45 3535.55,4289.45 U10.4@3580,4245
GPIO17: FPC2.5 U10.5 | length 296.9
  Top Layer w10: FPC2.5@3431.26,4340.15 3499.84,4340.15 3515,4325 3515,4235 3580,4170 U10.5@3580,4145
PTC: FPC1.4 R7.1 | length 1642.7
  Top Layer w10: v1(3655,3480) 3695.47,3439.53 FPC1.4@3695.47,3378.18 ; R7.1@3765,4805.34 3765,4800 v1(3795,4770)
  Bottom Layer w10: v1(3655,3480) 3655,3510 3950,3805 3950,4485 3845,4590 3845,4720 v1(3795,4770)
SCK: U8.11 U9.2 | length 591.3
  Top Layer w10: U8.11@3680,3688 3680,3580 3735,3525 3965,3525 4055.32,3434.68 U9.2@4055.32,3386.93
SPK1: SPK2.1 U7.14 | length 183.3
  Top Layer w15: U7.14@4040,4335.98 4040,4258.77 SPK2.1@4115,4183.77
SPK2: SPK2.2 U7.13 | length 372.6
  Top Layer w15: U7.13@3990,4335.98 3990,4280 4000,4270 4000,4133.72 SPK2.2@4117.5,4016.22
SW: FPC1.10 R3.2 U3.10 U9.4 U9.8 | length 2635
  Top Layer w10: FPC1.10@3813.59,3378.18 3815.41,3380 3965,3380 4005.31,3339.69 4084.69,3339.69 4094.69,3349.69 U9.4@4094.69,3386.93 4094.69,3503.36 4078.19,3519.86 4078.19,3549.88 U9.8@4075,3553.07 v1(4075,3635) ; R3.2@4145,5525.34 4145,5465.32 U3.10@4130.43,5450.75 4164.25,5450.75 4172.86,5442.14 4172.86,5357.86 v1(4155,5340)
  Bottom Layer w10: v1(4075,3635) 4075,3865 4145,3935 4145,4277.73 4085,4337.73 4085,5050 4172.86,5137.86 4172.86,5322.14 v1(4155,5340)
USBDM: U3.6 U7.4 | length 888.6
  Top Layer w10: U7.4@3990,4554.02 3990,4610 4010,4630 v1@4010,4655 ; v1(4070,5365) 4087.13,5382.13 U3.6@4087.13,5407.44
  Bottom Layer w10: v1(4010.05,4660) 4010.05,5305.05 v1(4070,5365)
USBDP: U3.7 U7.5 | length 995.8
  Top Layer w10: U7.5@3940,4554.02 3940,4605 3970,4635 v1(3970,4660) ; U3.7@4102.87,5407.44 4102.87,5357.13 v1(4105,5355)
  Bottom Layer w10: v1(3970,4660) 3970,4655 3995,4630 4015,4630 4040,4655 4040,5290 4040.55,5290.55 4040.55,5293.01 4102.54,5355 v1(4105,5355)
VIN: C1.1 C2.1 DC1.1 PTC1.1 R4.2 R13.1 U1.A4 U1.A9 U1.B4 U1.B9 U4.4 U4.5 | length 1893.5
  Top Layer w10: U1.A9@3874.61,5746.88 3875.03,5747.3 3875.03,5769.97 3910.06,5805 ; U1.B4@3886.42,5746.88 3886.42,5780 3887.93,5780 ; 4035,5830 4063.58,5801.42 U1.B9@4063.58,5746.88 U1.A4@4070,5740.46 ; 4138.5,4928.5 4159.66,4907.33 R13.1@4159.66,4720
  Top Layer w15: U1.A9@3874.61,5746.88 v1(3874.61,5711.35) 3874.61,5690.39 v1(3880,5685) ; U1.A4@4070,5740.46 v1(4070,5710) v1(4090,5690)
  Top Layer w20: 3875,5320 3930,5375 R4.2@3930,5395.34 ; 3995.78,4890.4 4100.4,4890.4 4138.5,4928.5 4167.86,4957.86 4167.86,5172.14 PTC1.1@4085,5255
  Top Layer w80: DC1.1@3552.51,5532.96 3552.51,5422.48 3680,5295 4045,5295 PTC1.1@4085,5255
pads on no net: FPC2.6 FPC2.7 FPC2.8 U1.A8 U1.B8 U2.2 U2.3 U2.6 U2.7 U2.10 U5.4 U7.1 U7.2 U7.3 U7.6 U7.7 U8.9 U8.10 U8.13

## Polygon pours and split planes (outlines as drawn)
$2N173 on Bottom Layer (solid, remove dead copper, pour order 4): 3670,5390 3955,5390 cw(c3955,5380) 3965,5380 3965,4929.48 cw(c3955,4929.48) 3955,4919.48 3670,4919.48 cw(c3670,4929.48) 3660,4929.48 3660,5380 cw(c3670,5380)
GND on Bottom Layer (solid, remove dead copper, pour order 6): 3010,6205 4400,6205 4400,3015 3010,3015
GND on Top Layer (solid, remove dead copper, pour order 0): 3000,6190 4390,6190 4390,3000 3000,3000
VIN on Bottom Layer (solid, remove dead copper, pour order 2): 3854.92,5731.88 4106.89,5731.88 4106.89,5680.48 4100.98,5674.58 3855,5674.58 3854.92,5674.66

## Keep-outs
Top Layer:
  region: 3275,5285 3400,5285 3400,5105 3275,5105
  region: 3250,5380 3250,4725 3555.78,4725 3555.78,5119.22 3555,5120 3605,5120 3605,5380
Bottom Layer:
  region: 3610,5790 3795,5790 3795,5755 3750.88,5755 3750.88,5439.86 3630,5315.96 3630,5106.96 3675,5071.23 3675,4634.16 3790,4528.8 3813.11,4503.11 3815,4470 3750,4470 3750,4493.56 3640,4600.47 3640,5037.17 3589.6,5089.31 3589.6,5334.53 3705,5445 3705,5760 3610,5760
Board Outline Layer:
  circle w1: c3294,5838.89 r35.43
  circle w10: c3294,5838.89 r35.43
  circle w1: c3294,3240.47 r35.43
  circle w10: c3294,3240.47 r35.43
  circle w1: c4140.46,3240.47 r35.43
  circle w10: c4140.46,3240.47 r35.43
  region: 3750,4602.56 3822.99,4602.56 3822.99,4468.08 3750,4468.08
  lines w7.87: 3244.79,3181.58 3244.79,5897.79 cw(c3254.79,5897.79) 3254.79,5907.79 3726.91,5907.79 ccw(c3726.91,5917.79) 3736.91,5917.79 3736.91,5976.53 cw(c3746.91,5976.53) 3746.91,5986.53 4179.67,5986.53 cw(c4179.67,5976.53) 4189.67,5976.53 4189.67,3181.58 cw(c4179.67,3181.58) 4179.67,3171.58 3254.79,3171.58 cw(c3254.79,3181.58) 3244.79,3181.58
